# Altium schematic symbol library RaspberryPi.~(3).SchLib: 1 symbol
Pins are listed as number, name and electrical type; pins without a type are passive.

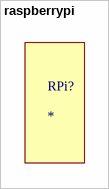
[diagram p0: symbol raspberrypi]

## raspberrypi
designator RPi?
